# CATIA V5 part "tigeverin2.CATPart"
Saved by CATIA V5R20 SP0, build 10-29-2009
Part number: tigeverin2
Bounding box of the stored display mesh (mm): x 50 to 270, y -210 to -190, z 17 to 37
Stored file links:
  D:\Dropbox\Pack 1 sylvain\mmoreau\mmoreau\mmoreau\fin\tigeverin2.CATPart
  U:\think motion\fin\think motion2.CATProduct
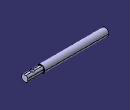
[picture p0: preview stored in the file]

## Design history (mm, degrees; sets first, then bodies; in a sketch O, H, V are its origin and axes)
External parameters (linked from other documents)
  `External.longueur tige verin2` = 200 mm
Set1
  Plane1: linked copy from another document
  Line1: linked copy from another document
  Point1: linked copy from another document
Body1 (main body)
  Sketch1 on Plane1, origin (50, 0, 0), H (0, 1, 0), V (0, 0, 1)
    line L1 (-208, 35) -> (-192, 35)
    line L2 (-192, 35) -> (-192, 19)
    line L3 (-192, 19) -> (-208, 19)
    line L4 (-208, 19) -> (-208, 35)
    reference projected point E1 (-200, 30) from Line1
    reference projected point E2 (-200, 30) from Point1
    distance E1 L4 = 8
    distance L2 L4 = 16 {= Sketch1.distance(E1 L4) *2}
    distance L3 L1 = 16
    distance E2 L1 = 5
    horizontal: L1 H, L3 H
    vertical: L2 V, L4 V
  Pad1: profile Sketch1, direction (1, 0, 0), length 220 {= `External.longueur tige verin2` +20mm}
  Fillet1: radius 5, on edge [face of Pad1 from Sketch1.L4 | face of Pad1 from Sketch1.L1]; edge [face of Pad1 from Sketch1.L1 | face of Pad1 from Sketch1.L2]; edge [face of Pad1 from Sketch1.L3 | face of Pad1 from Sketch1.L4]; edge [face of Pad1 from Sketch1.L2 | face of Pad1 from Sketch1.L3]
  Sketch2 on face of Pad1 from Sketch1.L1, origin (217.0252, -199.0324, 35), H (1, 0, 0), V (0, 1, 0)
    point P1 (32.9748, -0.9676)
    reference projected point E1 (32.9748, -0.9676) from Point1
    coincidence: E1 P1
  Hole1: placed by Sketch2, at (250, -200, 35) direction (0, 0, -1), diameter 10, through (limit type 3)
  Sketch3 on Plane1, origin (50, 0, 0), H (0, 1, 0), V (0, 0, 1)
    circle A1 centre (-200, 27) radius 10
    point P1 (-200, 27)
    reference projected point E1 (-200, 30) from Point1
    reference projected point E2 (-200, 30) from Point1
    distance P1 E1 H = 0
    distance P1 E2 = 3
    radius A1 = 10
  Pad2: profile Sketch3, direction (1, 0, 0), length 175
  Fillet2: radius 1, on edge [face of Pad1 from Sketch1.L1 | end face of Pad2]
